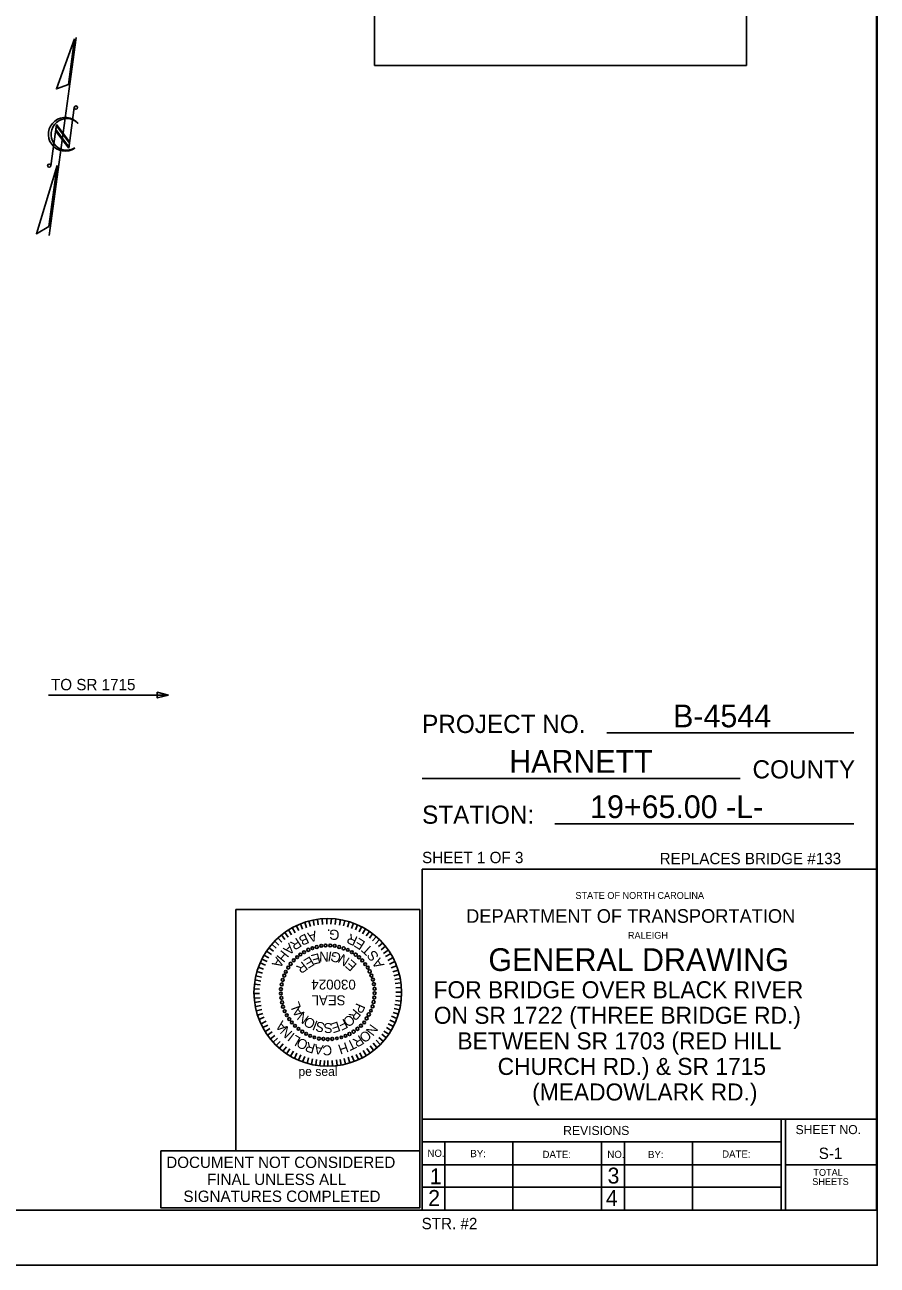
# Model space of a CAD drawing. Extents: x 985 to 1514, y -701 to -21.
# Drawn here: x 1188.2 to 1263.2, y -220.9 to -111.7 of the extents above; entities that cross this region are included whole.
import ezdxf

# ---------------------------------------------------------------- set-up
doc = ezdxf.new("R2010")
doc.units = 0
for name, color, linetype in [('Arrowhead Terminators CELL', 7, 'Continuous'), ('Dimension Lines', 7, 'Continuous'), ('Peseal', 7, 'Continuous'), ('Plan Sheet CELL', 7, 'Continuous'), ('Plot Shape CELL', 7, 'Continuous'), ('Sheet North Arrow CELL', 7, 'Continuous'), ('Sheet Sticker Exception Certification CELL', 7, 'Continuous'), ('Subtitle Text', 7, 'Continuous'), ('Text', 7, 'Continuous'), ('Title Text', 7, 'Continuous'), ('User Information Notes', 7, 'Continuous'), ('User Information Notes CELL', 7, 'Continuous')]:
    doc.layers.add(name, color=color, linetype=linetype)

msp = doc.modelspace()

# ---------------------------------------------------------------- linework, layer by layer
at = {"layer": 'Arrowhead Terminators CELL'}
msp.add_lwpolyline([(1200.84, -170.74), (1199.84, -170.49), (1199.84, -170.99)], close=True, dxfattribs=at)
at = {"layer": 'Dimension Lines'}
msp.add_line((1190.26, -170.74), (1200.84, -170.74), dxfattribs=at)
at = {"layer": 'Peseal'}
for p, q in [((1212.3, -191.47), (1212.08, -191.03)), ((1212.64, -191.34), (1212.45, -190.87)), ((1212.98, -191.22), (1212.83, -190.72)), ((1213.33, -191.09), (1213.2, -190.62)), ((1213.67, -191.03), (1213.58, -190.53)), ((1214.02, -190.97), (1213.95, -190.47)), ((1214.39, -190.94), (1214.36, -190.44)), ((1214.77, -190.91), (1214.77, -190.41)), ((1215.14, -190.91), (1215.17, -190.41)), ((1215.52, -190.94), (1215.58, -190.44)), ((1215.89, -191), (1215.98, -190.5)), ((1216.23, -191.06), (1216.36, -190.59)), ((1216.58, -191.16), (1216.73, -190.69)), ((1216.95, -191.28), (1217.11, -190.81)), ((1217.3, -191.41), (1217.48, -190.97)), ((1210.8, -192.47), (1210.48, -192.12)), ((1211.08, -192.25), (1210.77, -191.84)), ((1211.36, -192.03), (1211.08, -191.62)), ((1211.67, -191.84), (1211.39, -191.41)), ((1211.98, -191.66), (1211.73, -191.19)), ((1217.61, -191.56), (1217.83, -191.12)), ((1217.92, -191.75), (1218.17, -191.31)), ((1218.23, -191.94), (1218.52, -191.53)), ((1218.52, -192.12), (1218.8, -191.75)), ((1218.8, -192.37), (1219.11, -192)), ((1210.08, -193.28), (1209.67, -192.97)), ((1210.3, -193), (1209.92, -192.66)), ((1210.55, -192.75), (1210.17, -192.37)), ((1219.05, -192.62), (1219.42, -192.25)), ((1219.33, -192.87), (1219.67, -192.56)), ((1219.55, -193.16), (1219.95, -192.84)), ((1219.77, -193.47), (1220.17, -193.19)), ((1209.36, -194.5), (1208.89, -194.31)), ((1209.52, -194.19), (1209.05, -193.97)), ((1209.67, -193.87), (1209.23, -193.62)), ((1209.89, -193.56), (1209.45, -193.28)), ((1219.95, -193.75), (1220.39, -193.5)), ((1220.14, -194.09), (1220.61, -193.84)), ((1220.3, -194.41), (1220.77, -194.19)), ((1209.02, -195.56), (1208.52, -195.44)), ((1209.11, -195.22), (1208.61, -195.06)), ((1209.2, -194.87), (1208.73, -194.69)), ((1220.45, -194.75), (1220.92, -194.56)), ((1220.58, -195.09), (1221.05, -194.94)), ((1220.67, -195.44), (1221.17, -195.31)), ((1208.89, -196.25), (1208.39, -196.19)), ((1208.95, -195.91), (1208.45, -195.81)), ((1220.77, -195.78), (1221.23, -195.69)), ((1220.8, -196.12), (1221.3, -196.06)), ((1220.86, -196.5), (1221.36, -196.47)), ((1208.86, -196.62), (1208.36, -196.59)), ((1208.86, -197), (1208.36, -197)), ((1208.89, -197.37), (1208.39, -197.41)), ((1220.86, -196.87), (1221.36, -196.87)), ((1220.86, -197.25), (1221.36, -197.28)), ((1208.92, -197.72), (1208.42, -197.78)), ((1208.98, -198.06), (1208.48, -198.16)), ((1209.05, -198.41), (1208.58, -198.53)), ((1220.61, -198.66), (1221.08, -198.81)), ((1220.7, -198.31), (1221.17, -198.44)), ((1220.77, -197.97), (1221.27, -198.06)), ((1220.83, -197.62), (1221.3, -197.69)), ((1209.14, -198.75), (1208.67, -198.91)), ((1209.27, -199.09), (1208.8, -199.28)), ((1209.42, -199.44), (1208.98, -199.66)), ((1209.58, -199.78), (1209.14, -200)), ((1220.17, -199.66), (1220.64, -199.91)), ((1220.33, -199.34), (1220.8, -199.56)), ((1220.48, -199), (1220.95, -199.19)), ((1209.77, -200.09), (1209.36, -200.34)), ((1209.95, -200.37), (1209.55, -200.66)), ((1210.2, -200.69), (1209.8, -201)), ((1219.36, -200.87), (1219.73, -201.19)), ((1219.61, -200.59), (1219.98, -200.87)), ((1219.8, -200.31), (1220.23, -200.59)), ((1220.02, -200), (1220.45, -200.25)), ((1210.42, -200.94), (1210.05, -201.28)), ((1210.67, -201.22), (1210.33, -201.56)), ((1210.92, -201.44), (1210.61, -201.81)), ((1211.23, -201.69), (1210.92, -202.06)), ((1211.52, -201.87), (1211.23, -202.31)), ((1218.3, -201.84), (1218.58, -202.25)), ((1218.58, -201.62), (1218.89, -202)), ((1218.86, -201.37), (1219.17, -201.75)), ((1219.11, -201.12), (1219.48, -201.5)), ((1211.83, -202.09), (1211.58, -202.53)), ((1212.14, -202.25), (1211.92, -202.72)), ((1212.48, -202.41), (1212.27, -202.87)), ((1212.83, -202.56), (1212.64, -203.03)), ((1213.17, -202.66), (1213.05, -203.16)), ((1213.52, -202.75), (1213.42, -203.25)), ((1213.86, -202.81), (1213.8, -203.31)), ((1214.23, -202.87), (1214.17, -203.37)), ((1214.58, -202.91), (1214.55, -203.41)), ((1214.86, -202.91), (1214.86, -203.41)), ((1215.23, -202.91), (1215.27, -203.41)), ((1215.61, -202.84), (1215.67, -203.34)), ((1215.95, -202.81), (1216.05, -203.31)), ((1216.3, -202.72), (1216.42, -203.22)), ((1216.64, -202.62), (1216.8, -203.12)), ((1216.98, -202.5), (1217.17, -202.97)), ((1217.36, -202.37), (1217.55, -202.81)), ((1217.67, -202.22), (1217.89, -202.66)), ((1217.98, -202.03), (1218.23, -202.47))]:
    msp.add_line(p, q, dxfattribs=at)
for centre, radius in [((1212.77, -193.36), 0.126), ((1213.14, -193.16), 0.14), ((1213.5, -193.01), 0.119), ((1213.89, -192.91), 0.129), ((1214.28, -192.81), 0.126), ((1214.67, -192.78), 0.125), ((1215.08, -192.78), 0.125), ((1215.47, -192.81), 0.126), ((1215.86, -192.91), 0.129), ((1216.25, -193.03), 0.134), ((1216.63, -193.17), 0.119), ((1216.98, -193.36), 0.126), ((1211.59, -194.39), 0.134), ((1211.86, -194.08), 0.122), ((1212.16, -193.81), 0.122), ((1212.44, -193.56), 0.122), ((1217.31, -193.58), 0.134), ((1217.61, -193.81), 0.133), ((1217.89, -194.09), 0.133), ((1218.14, -194.42), 0.122), ((1211.02, -195.42), 0.134), ((1211.16, -195.09), 0.126), ((1211.38, -194.72), 0.126), ((1218.38, -194.72), 0.126), ((1218.55, -195.06), 0.14), ((1218.7, -195.42), 0.134), ((1210.73, -196.61), 0.126), ((1210.8, -196.2), 0.126), ((1210.89, -195.81), 0.129), ((1218.83, -195.78), 0.129), ((1218.92, -196.17), 0.126), ((1218.98, -196.58), 0.126), ((1210.73, -197), 0.125), ((1210.77, -197.39), 0.126), ((1218.89, -197.75), 0.129), ((1218.95, -197.36), 0.126), ((1218.98, -196.97), 0.125), ((1210.83, -197.78), 0.129), ((1210.92, -198.17), 0.134), ((1211.06, -198.55), 0.119), ((1218.47, -198.84), 0.144), ((1218.66, -198.51), 0.119), ((1218.8, -198.14), 0.134), ((1211.25, -198.91), 0.126), ((1211.47, -199.25), 0.126), ((1211.7, -199.55), 0.122), ((1211.97, -199.84), 0.122), ((1217.77, -199.84), 0.133), ((1218.06, -199.55), 0.11), ((1218.28, -199.2), 0.134), ((1212.28, -200.12), 0.122), ((1212.61, -200.36), 0.126), ((1212.95, -200.55), 0.126), ((1213.31, -200.73), 0.119), ((1213.67, -200.86), 0.114), ((1214.08, -200.97), 0.129), ((1214.47, -201), 0.126), ((1215.25, -201), 0.126), ((1215.66, -200.95), 0.11), ((1216.05, -200.86), 0.114), ((1216.41, -200.73), 0.119), ((1216.77, -200.56), 0.14), ((1217.13, -200.36), 0.134), ((1217.47, -200.11), 0.134), ((1214.86, -201.03), 0.125)]:
    msp.add_circle(centre, radius, dxfattribs=at)
at = {"layer": 'Plan Sheet CELL'}
for p, q in [((1263.16, -48.07), (1263.16, -216.07)), ((1261.16, -174.07), (1239.42, -174.07)), ((1251.16, -178.07), (1223.16, -178.07)), ((1261.16, -182.06), (1234.84, -182.06)), ((1263.16, -186.06), (1223.16, -186.06)), ((1223.16, -186.06), (1223.16, -216.07)), ((1223.16, -208.07), (1263.16, -208.07)), ((1254.76, -208.07), (1254.76, -216.07)), ((1255.16, -208.07), (1255.16, -216.07)), ((1223.16, -210.06), (1254.77, -210.06)), ((1223.18, -210.06), (1223.18, -216.07)), ((1225.16, -210.06), (1225.16, -216.07)), ((1231.16, -210.1), (1231.16, -216.1)), ((1238.96, -210.06), (1238.96, -216.12)), ((1240.97, -210.06), (1240.97, -216.07)), ((1246.97, -210.06), (1246.97, -216.07)), ((1223.16, -212.07), (1254.84, -212.07)), ((1255.16, -212.07), (1263.09, -212.07)), ((1223.16, -214.06), (1254.77, -214.06)), ((1007.15, -216.07), (1263.16, -216.07)), ((1263.23, -220.92), (1263.23, -220.92))]:
    msp.add_line(p, q, dxfattribs=at)
msp.add_lwpolyline([(1218.98, -115.31), (1251.72, -115.31), (1251.72, -93.31), (1218.98, -93.31)], close=True, dxfattribs=at)
at = {"layer": 'Plot Shape CELL'}
msp.add_lwpolyline([(998.72, -44.92), (1263.23, -44.92), (1263.23, -220.92), (998.72, -220.92)], close=True, dxfattribs=at)
at = {"layer": 'Sheet North Arrow CELL'}
for p, q in [((1190.33, -130.28), (1192.71, -112.84)), ((1192.54, -119), (1192.05, -122.58)), ((1190.98, -120.5), (1190.48, -124.14)), ((1192.05, -122.58), (1190.9, -121.06)), ((1190.96, -120.63), (1190.91, -120.96)), ((1192.06, -122.48), (1190.91, -120.96)), ((1190.91, -120.96), (1192.06, -122.48)), ((1192.11, -122.15), (1190.96, -120.63)), ((1192.13, -122.02), (1190.98, -120.5)), ((1192.85, -120.4), (1192.87, -120.41)), ((1192.06, -122.48), (1192.11, -122.15))]:
    msp.add_line(p, q, dxfattribs=at)
for points in [[(1192.57, -112.97), (1190.96, -117.37), (1192.02, -117)], [(1191.03, -124.11), (1189.2, -130.12), (1190.29, -129.48)]]:
    msp.add_lwpolyline(points, close=True, dxfattribs=at)
for centre in [(1192.68, -119.02), (1190.34, -124.13)]:
    msp.add_circle(centre, 0.144, dxfattribs=at)
for centre, radius, start, end in [((1191.74, -121.37), 1.48, 40.0635, 304.6175), ((1191.88, -121.38), 1.39, 45.3185, 300.8522)]:
    msp.add_arc(centre, radius, start, end, dxfattribs=at)
at = {"layer": 'Sheet Sticker Exception Certification CELL'}
msp.add_lwpolyline([(1200.17, -210.85), (1222.96, -210.85), (1222.96, -215.87), (1200.17, -215.87)], close=True, dxfattribs=at)
at = {"layer": 'User Information Notes'}
for p, q in [((1251.72, -115.31), (1251.72, -115.31)), ((1214.86, -196.91), (1214.86, -196.91))]:
    msp.add_line(p, q, dxfattribs=at)
at = {"layer": 'User Information Notes CELL'}
msp.add_line((1214.86, -196.91), (1214.86, -196.91), dxfattribs=at)
msp.add_lwpolyline([(1206.76, -189.61), (1222.96, -189.61), (1222.96, -210.85), (1206.76, -210.85)], close=True, dxfattribs=at)
msp.add_circle((1214.86, -196.91), 6.5, dxfattribs=at)

# ---------------------------------------------------------------- texts
at = {"layer": 'Dimension Lines'}
msp.add_text('STR. #2', height=1, dxfattribs=at).set_placement((1223.12, -217.75))
at = {"layer": 'Peseal'}
for s, height, rotation, p in [('R', 0.887, 213.5776, (1212.16, -192.05)), ('B', 0.887, 204.8312, (1212.93, -191.7)), ('A', 0.887, 195.7955, (1213.77, -191.46)), ('.', 0.887, 182.1323, (1215.09, -191.35)), ('G', 0.887, 173.3858, (1215.93, -191.45)), ('R', 0.888, 155.458, (1217.56, -192.05)), ('E', 0.887, 147.1453, (1218.23, -192.49)), ('H', 0.887, 231.3597, (1210.81, -193.11)), ('A', 0.887, 222.3241, (1211.45, -192.52)), ('T', 0.887, 138.1096, (1218.88, -193.07)), ('S', 0.887, 129.4349, (1219.41, -193.72)), ('A', 0.887, 239.6007, (1210.3, -193.73)), ('R', 0.875, 218.6997, (1212.64, -194.12)), ('E', 0.875, 210.6815, (1213.33, -193.69)), ('E', 0.875, 194.6452, (1214.08, -193.44)), ('N', 0.875, 178.6088, (1214.95, -193.34)), ('I', 0.875, 170.5906, (1215.27, -193.34)), ('G', 0.875, 162.5725, (1216.11, -193.53)), ('N', 0.875, 146.5361, (1216.86, -193.94)), ('E', 0.875, 138.5179, (1217.48, -194.47)), ('A', 0.887, 120.3993, (1219.86, -194.48)), ('030024', 0.875, 180, (1217.32, -195.78)), ('SEAL', 0.875, 180, (1216.42, -197.16)), ('L', 0.875, 110.0824, (1212.52, -198.25)), ('A', 0.875, 126.1483, (1212.83, -198.69)), ('N', 0.875, 142.2141, (1213.27, -199.06)), ('R', 0.875, 230.5765, (1217.17, -198.28)), ('P', 0.875, 246.6424, (1217.39, -197.78)), ('A', 0.875, 128.6477, (1211.36, -199.94)), ('O', 0.875, 150.2471, (1213.86, -199.44)), ('I', 0.875, 158.28, (1214.05, -199.47)), ('S', 0.875, 166.313, (1214.67, -199.62)), ('S', 0.875, 182.3789, (1215.27, -199.59)), ('E', 0.875, 198.4448, (1215.77, -199.44)), ('F', 0.875, 206.4777, (1216.33, -199.19)), ('O', 0.875, 222.5436, (1216.77, -198.78)), ('N', 0.875, 234.0504, (1218.64, -199.62)), ('N', 0.875, 135.6745, (1211.8, -200.41)), ('I', 0.875, 142.7014, (1212.02, -200.59)), ('L', 0.875, 149.7282, (1212.55, -200.94)), ('R', 0.875, 212.9699, (1217.67, -200.62)), ('O', 0.875, 219.9967, (1218.23, -200.16)), ('O', 0.875, 156.7551, (1213.2, -201.22)), ('R', 0.875, 163.7819, (1213.83, -201.47)), ('A', 0.875, 170.8088, (1214.52, -201.56)), ('C', 0.875, 184.8625, (1215.2, -201.53)), ('H', 0.875, 198.9162, (1216.48, -201.28)), ('T', 0.875, 205.943, (1217.08, -200.97))]:
    msp.add_text(s, height=height, rotation=rotation, dxfattribs=at).set_placement(p)
at = {"layer": 'Plan Sheet CELL'}
for s, height, p in [('PROJECT NO.', 1.6, (1223.16, -174.07)), ('COUNTY', 1.6, (1252.25, -178.07)), ('STATION:', 1.6, (1223.16, -182.06)), ('SHEET 1 OF 3', 1, (1223.16, -185.53)), ('STATE OF NORTH CAROLINA', 0.6, (1236.66, -188.67)), ('DEPARTMENT OF TRANSPORTATION', 1.2, (1227.04, -190.78)), ('RALEIGH', 0.6, (1241.28, -192.18)), ('REVISIONS', 0.8, (1235.58, -209.46)), ('SHEET NO.', 0.8, (1256.04, -209.38)), ('NO.', 0.637, (1223.63, -211.38)), ('BY:', 0.637, (1227.41, -211.41)), ('DATE:', 0.637, (1233.76, -211.48)), ('NO.', 0.637, (1239.47, -211.48)), ('BY:', 0.637, (1243.05, -211.49)), ('DATE:', 0.637, (1249.57, -211.45)), ('1', 1.4, (1223.84, -213.79)), ('3', 1.4, (1239.49, -213.73)), ('TOTAL', 0.6, (1257.61, -213.05)), ('SHEETS', 0.6, (1257.51, -213.86)), ('2', 1.4, (1223.7, -215.7)), ('4', 1.4, (1239.34, -215.7))]:
    msp.add_text(s, height=height, dxfattribs=at).set_placement(p)
at = {"layer": 'Sheet Sticker Exception Certification CELL'}
for s, p in [('DOCUMENT NOT CONSIDERED', (1200.64, -212.36)), ('FINAL UNLESS ALL', (1204.23, -213.86)), ('SIGNATURES COMPLETED', (1202.15, -215.35))]:
    msp.add_text(s, height=0.9978, dxfattribs=at).set_placement(p)
at = {"layer": 'Subtitle Text'}
for s, p in [('FOR BRIDGE OVER BLACK RIVER', (1224.17, -197.42)), ('ON SR 1722 (THREE BRIDGE RD.)', (1224.19, -199.67)), ('BETWEEN SR 1703 (RED HILL', (1226.27, -201.92)), ('CHURCH RD.) & SR 1715', (1229.81, -204.17)), ('(MEADOWLARK RD.)', (1232.85, -206.42))]:
    msp.add_text(s, height=1.5, dxfattribs=at).set_placement(p)
at = {"layer": 'Text'}
for s, p in [('TO SR 1715', (1190.49, -170.31)), ('REPLACES BRIDGE #133', (1244.07, -185.62)), ('S-1', (1258.08, -211.57))]:
    msp.add_text(s, height=1, dxfattribs=at).set_placement(p)
at = {"layer": 'Title Text'}
for s, p in [('B-4544', (1245.26, -173.57)), ('HARNETT', (1230.83, -177.57)), ('19+65.00 -L-', (1237.95, -181.56)), ('GENERAL DRAWING', (1229, -195.02))]:
    msp.add_text(s, height=2, dxfattribs=at).set_placement(p)
at = {"layer": 'User Information Notes CELL'}
msp.add_text('pe seal', height=0.8, dxfattribs=at).set_placement((1212.27, -204.26))

doc.saveas('drawing.dxf')
